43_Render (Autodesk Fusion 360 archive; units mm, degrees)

design "43 Render"
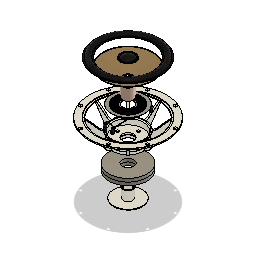
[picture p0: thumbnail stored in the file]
part number: 6 Inch Woofer
parameter "VoiceCoilDia" = 30
parameter "VoiceCoilThickness" = 2
parameter "PoleDia" = 22 (= "VoiceCoilDia + -4 * VoiceCoilThickness")
parameter "BasketThickness" = 3
parameter "SpiderMountingSurface" = 46 (= "SpacerDiameter / 2 + 2 * BasketThickness")
parameter "adsk_nomlen" = 10
parameter "adsk_headh" = 2.7
parameter "adsk_headdia" = 9.3
parameter "adsk_nomdia" = 5
parameter "adsk_headang" = 90
parameter "adsk_phildia" = 5.2
parameter "adsk_philwidth" = 0.66
parameter "adsk_phildepth" = 3.2
parameter "adsk_shnkdia" = 4.5092
parameter "adsk_thrlen" = 5.7
parameter "adsk_pitch1" = 0.8
parameter "adsk_startlen" = 0.4908
parameter "adsk_midfillet" = 0.5 (= "adsk_nomdia * 0.1")
parameter "adsk_endpointdia" = 4.0185
parameter "MountingHoleDia" = 86.2 (= "( ( SpeakerSize * 25.4 / 2 ) * 1 mm ) + ( FlangeSize / 2 )")
parameter "ConeAngle" = 70
parameter "CoverThickness" = 2.5
sketch "Sketch1" plane through (0, 0, 0) normal (0, 1, 0) x axis (1, 0, 0)
  circle C1 centre (0, 0) radius 50
  circle C2 centre (0, 0) radius 18
  point P1 (0, 0)
  point P2 (0, 0)
  point P3 (0, 0)
  coincident P1 P2
  coincident P1 P3
  dimension "MagnetDia" diameter C1 = 100
  dimension "MagnetThruHole" diameter C2 = 36 (= "VoiceCoilDia + 3 * VoiceCoilThickness")
extrude "Extrude1" new body sketch "Sketch1" along normal blind 10 named "MagnetThickness"
as_built_joint "As-built1"
chamfer "Chamfer2" distance 0.5
rectangular_pattern "R-Pattern1" uSpaceDistance 10 (= "MagnetThickness") vSpaceDistance 0
sketch "Sketch1" plane through (0, 0, 0) normal (0, -1, 0) x axis (1, 0, 0)
  circle C1 centre (0, 0) radius 18
  circle C2 centre (0, 0) radius 37.5
  circle C3 centre (0, 0) radius 18
  circle C4 centre (0, 0) radius 6
  circle C5 centre (0, 0) radius 49.5
  concentric C1 C2
  concentric C2 C3
  concentric C2 C4
  dimension "BottomPlateDiameter" diameter C2 = 75 (= "MagnetDia * 0.75")
  dimension "d12" diameter C3 = 36 (= "MagnetThruHole")
  dimension "VentHole" diameter C4 = 12 (= "VoiceCoilDia / 2.5")
extrude "Extrude1" new body sketch "Sketch1" profile of C1 C2 C3 C4 along normal blind 9 (= "VentHole * 0.75") named "BottomPlateThickness"
fillet "Fillet1" radius 37.5 (= "BottomPlateDiameter / 2")
extrude "Extrude2" add of existing geometry blind 2 named "BottomPlateOffset"
fillet "Fillet2" radius 3 (= "VentHole / 4")
sketch "Sketch4" plane through (0, 2, 0) normal (0, 1, 0) x axis (-1, 0, 0)
  circle C1 centre (0, 0) radius 37.5
  circle C2 centre (0, 0) radius 15
  circle C3 centre (0, 0) radius 11
  circle C4 centre (0, 0) radius 9
  point P1 (0, 0)
  point P3 (0, 0)
  point P4 (0, 0)
  coincident P1 P3
  coincident P1 P4
  dimension "d23" diameter C2 = 30 (= "VoiceCoilDia")
  dimension "d24" diameter C3 = 22 (= "PoleDia")
extrude "Extrude3" add sketch "Sketch4" profile of C2 C3 along normal blind 30 (= "( MagnetCount + 1 ) * MagnetThickness") named "PoleLength"
chamfer "Chamfer1" distance 1
joint "Assemble" alignAngle 0 alignOffsetX 0 alignOffsetY 0 alignOffsetZ 0
sketch "Sketch1" plane through (0, 0, 0) normal (0, 1, 0) x axis (1, 0, 0)
  line L1 (0, 18) -> (0, 0)
  line L2 (0, 40) -> (0, 18)
  circle C1 centre (0, 0) radius 18
  circle C2 centre (0, 0) radius 40
  circle C3 centre (0, 0) radius 29
  point P1 (0, 0)
  point P2 (0, 0)
  point P3 (0, 0)
  point P4 (0, 0)
  point P5 (0, 18)
  point P6 (0, 40)
  point P8 (0, 29)
  coincident P1 P2
  coincident P1 P3
  coincident P2 P4
  coincident C1 P5
  vertical L1
  coincident C2 P6
  parallel L1 L2
  concentric C2 C3
  midpoint L2 P8
  coincident C3 P8
  dimension "d32" diameter C1 = 36 (= "MagnetThruHole")
  dimension "SpacerDiameter" diameter C2 = 80 (= "MagnetDia * 0.8")
extrude "Extrude1" new body sketch "Sketch1" profile of C1 C2 along normal blind 10 (= "MagnetThickness")
hole "Hole1" HoleDepth 10 (= "MagnetThickness") HoleDiameter 4.234 TipAngle 118
circular_pattern "C-Pattern1" countU 3 (= "SpeakerSize / 2") TotalAngle 360
chamfer "Chamfer1" distance 1
joint "Assemble" alignAngle 0 alignOffsetX 0 alignOffsetY 0 alignOffsetZ 0
sketch "Sketch1" plane through (0, 0, 0) normal (0, 1, 0) x axis (1, 0, 0)
  circle C1 centre (0, 0) radius 43
  circle C2 centre (0, 0) radius 18
  circle C3 centre (0, 29) radius 2.117
  point P1 (0, 0)
  point P2 (0, 0)
  point P3 (0, 0)
  coincident P1 P2
  coincident P1 P3
  dimension "d47" diameter C1 = 86 (= "SpacerDiameter + 2 * BasketThickness")
  dimension "d48" diameter C2 = 36 (= "MagnetThruHole")
extrude "Extrude1" new body sketch "Sketch1" against normal blind 5 (magnitude of "MagnetThickness / -2")
hole "Hole1" HoleDepth 10 HoleDiameter 5.5 TipAngle 118 CSDiameter 10.4 CSAngle 90
circular_pattern "C-Pattern1" countU 3 (= "SpeakerSize / 2") TotalAngle 360
joint "Assemble" alignAngle 0 alignOffsetX 0 alignOffsetY 0 alignOffsetZ 0
work_plane "WorkPlane1" RotateAngle 30 (= "90.0 deg - ( ( 360 / SpeakerSize ) * 1 deg )")
sketch "Sketch3" plane through (0, -22.875, 0) normal (0.5, 0, 0.866) x axis (0, 1, 0)
  line L1 (17.875, -43) -> (17.875, 43)
  line L2 (22.875, 43) -> (22.875, -43)
  line L3 (17.875, 18) -> (17.875, -18)
  line L4 (22.875, -18) -> (22.875, 18)
  line L5 (22.875, 18) -> (22.875, -18)
  line L6 (100, 0) -> (22.875, 0)
  line L7 (42.875, -46) -> (42.875, -43)
  line L8 (22.875, -46) -> (42.875, -46)
  line L9 (22.875, -43) -> (22.875, -46)
  line L10 (42.875, -43) -> (42.875, -46)
  line L11 (39.875, -46) -> (42.875, -46)
  line L12 (39.875, -43) -> (39.875, -46)
  line L13 (22.875, -43) -> (39.875, -43)
  line L14 (22.875, -40) -> (22.875, -43)
  line L15 (39.875, -40) -> (22.875, -40)
  line L16 (17.875, -53.0255) -> (17.875, -43)
  line L17 (60.975, -77.8667) -> (17.875, -53.0255)
  line L18 (60.975, -71.2) -> (46.9451, -56.2731)
  line L19 (60.975, -93.7) -> (60.975, -78.7)
  line L20 (65.475, -96.2) -> (60.975, -96.2)
  line L21 (65.475, -76.2) -> (65.475, -96.2)
  line L22 (60.975, -76.2) -> (65.475, -76.2)
  line L23 (60.975, -96.2) -> (60.975, -76.2)
  line L24 (22.875, -43) -> (17.875, -43)
  line L25 (17.875, -40) -> (17.875, -43)
  line L26 (22.875, -40) -> (17.875, -40)
  line L27 (63.225, -76.2) -> (60.975, -76.2)
  line L28 (63.225, -71.2) -> (63.225, -76.2)
  line L29 (60.975, -71.2) -> (63.225, -71.2)
  line L30 (60.975, -76.2) -> (60.975, -71.2)
  arc A1 centre (39.875, -43) radius 3 clockwise from (39.875, -40) to (42.875, -43)
  arc A2 centre (57.875, -46) radius 15 clockwise from (46.9451, -56.2731) to (42.875, -46)
  point P9 (22.875, -18)
  point P10 (22.875, -18)
  point P8 (22.875, 18)
  point P11 (22.875, 18)
  point P12 (22.875, 0)
  point P14 (42.875, 0)
  point P4 (22.875, -43)
  point P17 (22.875, -43)
  point P19 (22.875, -43)
  point P20 (22.875, -43)
  point P3 (17.875, -43)
  point P27 (17.875, -43)
  point P28 (60.975, -93.7)
  point P34 (60.975, -93.7)
  point P29 (60.975, -78.7)
  point P35 (60.975, -78.7)
  point P36 (60.975, -86.2)
  point P42 (17.875, -43)
  point P43 (17.875, -40)
  point P47 (60.975, -77.8667)
  point P15 (42.875, -46)
  point P39 (42.875, -46)
  point P22 (39.875, -43)
  point P26 (39.875, -43)
  point P23 (39.875, -43)
  point P37 (17.875, -53.0255)
  point P38 (17.875, -53.0255)
  point P16 (22.875, -46)
  point P18 (39.875, -46)
  point P30 (60.975, -96.2)
  point P31 (65.475, -96.2)
  point P32 (65.475, -76.2)
  point P33 (60.975, -76.2)
  point P44 (63.225, -76.2)
  point P45 (63.225, -71.2)
  point P46 (60.975, -71.2)
  coincident P9 P10
  coincident P8 P11
  midpoint L2 P12
  perpendicular L5 L6
  coincident L6 P14
  perpendicular L6 L7
  perpendicular L2 L8
  coincident P4 P17
  perpendicular L8 L9
  perpendicular L8 L10
  perpendicular L7 L11
  coincident P4 P19
  perpendicular L9 L13
  vertical L12
  coincident P4 P20
  perpendicular L13 L14
  horizontal L15
  coincident P14 L7
  tangent L7 A1
  tangent L15 A1
  coincident P3 P27
  parallel L1 L16
  vertical L19
  perpendicular L20 L21
  perpendicular L21 L22
  coincident P28 P34
  coincident P29 P35
  midpoint L19 P36
  perpendicular L20 L23
  midpoint P36 L23
  tangent L18 A2
  coincident P3 P42
  coincident L1 P43
  parallel L1 L25
  horizontal L26
  horizontal L27
  vertical L28
  horizontal L29
  vertical L30
  coincident L23 P47
  coincident P15 P39
  tangent L7 A2
  coincident P22 P26
  coincident P23 P26
  coincident P37 P38
  dimension "SpiderDepth" distance P15 P16 = 20
  dimension "d70" distance P15 P18 = 3 (= "BasketThickness")
  dimension "d73" radius A1 = 3 (= "BasketThickness")
  dimension "d75" distance P30 P31 = 4.5 (= "BasketThickness * 1.5")
  dimension "d77" distance L6 L22 = 76.2 (= "( SpeakerSize * 25.4 / 2 ) * 1 mm")
  dimension "FlangeSize" distance P31 P32 = 20
  dimension "d79" distance P34 P35 = 15 (= "FlangeSize * 0.75")
  dimension "d80" distance L2 L23 = 38.1 (= "( SpeakerSize * 25.4 / 4 ) * 1 mm")
  dimension "d84" radius A2 = 15
  dimension "d95" distance P33 P44 = 2.25 (= "BasketThickness * 0.75")
  dimension "d96" distance P44 P45 = 5 (= "FlangeSize / 4")
  dimension "d178" distance P46 P47 = 6.6667 (= "FlangeSize / 3")
  dimension "d252" distance L15 L24 = 3 (= "BasketThickness")
  dimension "d254" angle L17 L18 = 16.817
  dimension "d259" distance L6 L11 = 46 (= "SpiderMountingSurface")
revolve "Revolve1" sketch "Sketch3" AlongAngle 360
fillet "Fillet2" radius 3 (= "BasketThickness")
chamfer "Chamfer1" distance 1 distance 0.5
extrude "Extrude2" add sketch "Sketch3" profile of L1 L2 L10 L11 L12 L13 L14 L15 A1 L16 L17 L18 L19 L23 A2 L24 L25 L26 along a picked direction distance 3 (= "BasketThickness")
fillet "Fillet3" radius 12 (= "BasketThickness * 4")
chamfer "Chamfer2" distance 0.5
circular_pattern "C-Pattern2" TotalAngle 360
sketch "Sketch4" plane through (0, 42.6, 0) normal (0, 1, 0) x axis (-1, 0, 0)
  line L1 (0, -125) -> (0, 0)
  line L2 (-44.35, -76.8165) -> (0, 0)
  line L3 (-48.1, -83.3116) -> (-44.35, -76.8165)
  circle C1 centre (0, 0) radius 76.7
  circle C2 centre (0, 0) radius 95.7
  circle C3 centre (0, 0) radius 96.2
  point P1 (0, 0)
  point P3 (0, 0)
  point P5 (0, 0)
  point P8 (-48.1, -83.3116)
  point P6 (-44.35, -76.8165)
  coincident P1 P3
  vertical L1
  coincident P1 P5
  coincident C3 P8
  parallel L2 L3
  dimension "d97" angle L1 L2 = 30 (= "( 180 / SpeakerSize ) * 1 deg")
  dimension "d181" distance P6 P8 = 7.5
hole "Hole2" HoleDepth 20 HoleDiameter 5.5 TipAngle 118 CSDiameter 10.4 CSAngle 90
circular_pattern "C-Pattern3" countU 12 TotalAngle 360
sketch "Sketch1" plane through (0, 0, 0) normal (0, 0, 1) x axis (1, 0, 0)
  line L1 (0, 140.5455) -> (0, 0)
  line L2 (71.2, 76.35) -> (75.95, 76.35)
  line L3 (71.2, 75.35) -> (71.2, 76.35)
  line L4 (76.2, 75.35) -> (71.2, 75.35)
  line L5 (76.2, 76.1) -> (76.2, 75.35)
  line L6 (56.2, 76.35) -> (51.45, 76.35)
  line L7 (56.2, 75.35) -> (56.2, 76.35)
  line L8 (51.2, 75.35) -> (56.2, 75.35)
  line L9 (51.2, 76.1) -> (51.2, 75.35)
  line L10 (71.2, 75.35) -> (56.2, 75.35)
  line L11 (0, 50.963) -> (51.2, 75.35)
  line L12 (15, 58.1076) -> (51.2, 75.35)
  line L13 (15.285, 57.1357) -> (53.5255, 75.35)
  line L14 (15, 55.25) -> (15, 56.6843)
  line L15 (14.57, 57.9028) -> (15, 58.1076)
  line L16 (14, 55.25) -> (14, 57)
  line L17 (14.75, 55) -> (14.25, 55)
  line L18 (30.3147, 35) -> (19.9147, 35)
  line L19 (-19.9147, 35) -> (-30.3147, 35)
  line L20 (5.2, 35) -> (-5.2, 35)
  line L21 (-39, 20) -> (39, 20)
  line L22 (-40, 35) -> (40, 35)
  line L23 (18, 35) -> (-18, 35)
  circle C1 centre (63.7, 75.35) radius 7.5664
  circle C2 centre (63.7, 75.35) radius 8.5664
  arc A1 centre (75.95, 76.1) radius 0.25 clockwise from (75.95, 76.35) to (76.2, 76.1)
  arc A2 centre (51.45, 76.1) radius 0.25 clockwise from (51.2, 76.1) to (51.45, 76.35)
  arc A3 centre (15.5, 56.6843) radius 0.5 clockwise from (15, 56.6843) to (15.285, 57.1357)
  arc A4 centre (15, 57) radius 1 clockwise from (14, 57) to (14.57, 57.9028)
  arc A5 centre (14.75, 55.25) radius 0.25 clockwise from (15, 55.25) to (14.75, 55)
  arc A6 centre (14.25, 55.25) radius 0.25 clockwise from (14.25, 55) to (14, 55.25)
  point P1 (0, 0)
  point P2 (0, 0)
  point P6 (71.2, 75.35)
  point P10 (56.2, 75.35)
  point P12 (63.7, 75.35)
  point P9 (56.2, 76.35)
  point P14 (56.1336, 75.35)
  point P15 (55.1336, 75.35)
  point P16 (0, 50.963)
  point P17 (15, 58.1076)
  point P4 (76.2, 76.35)
  point P8 (51.2, 76.35)
  point P24 (53.5255, 75.35)
  point P25 (15, 57)
  point P26 (15, 55)
  point P7 (76.2, 75.35)
  point P11 (51.2, 75.35)
  coincident P1 P2
  vertical L1
  horizontal L2
  vertical L3
  horizontal L4
  vertical L5
  horizontal L6
  vertical L7
  horizontal L8
  vertical L9
  horizontal P6 P10
  midpoint L10 P12
  coincident P9 C1
  concentric C1 C2
  coincident C1 P14
  coincident L8 P14
  coincident L8 P15
  coincident C2 P15
  coincident L1 P16
  coincident L11 P17
  coincident P4 L2
  coincident P4 L5
  tangent L2 A1
  tangent L5 A1
  coincident P8 L6
  coincident P8 L9
  tangent L6 A2
  tangent L9 A2
  coincident L8 P24
  parallel L12 L13
  vertical P17 P25
  vertical L14
  parallel L14 L16
  horizontal L17
  coincident P25 L13
  coincident P25 L14
  tangent L13 A3
  tangent L14 A3
  tangent L15 A4
  tangent L16 A4
  parallel L12 L15
  coincident P26 L14
  coincident P26 L17
  tangent L14 A5
  tangent L17 A5
  tangent L16 A6
  tangent L17 A6
  equal A5 A6
  dimension "SurroundThickness" distance P4 P7 = 1
  dimension "d107" distance P8 P11 = 1 (= "SurroundThickness")
  dimension "d108" distance P6 P7 = 5 (= "FlangeSize / 4")
  dimension "d109" distance P10 P11 = 5 (= "FlangeSize / 4")
  dimension "SurroundSize" distance L3 L7 = 15 (= "FlangeSize * 0.75")
  dimension "d111" distance P14 P15 = 1 (= "SurroundThickness")
  dimension "d112" distance L1 L5 = 76.2 (= "( SpeakerSize * 25.4 / 2 ) * 1 mm")
  dimension "d117" radius A1 = 0.25
  dimension "d118" radius A2 = 0.25
  dimension "d119" distance L12 L13 = 1 (= "SurroundThickness")
  dimension "d120" distance P25 P26 = 2 (= "SurroundThickness * 2")
  dimension "d121" distance L14 L16 = 1 (= "SurroundThickness")
  dimension "d122" radius A3 = 0.5 (= "SurroundThickness / 2")
  dimension "d123" radius A4 = 1 (= "SurroundThickness")
  dimension "d124" radius A5 = 0.25 (= "SurroundThickness / 4")
  dimension "d141" distance L1 L14 = 15 (= "VoiceCoilDia / 2")
  dimension "d144" distance L17 L21 = 35 (= "VoiceCoilLength")
  dimension "d282" distance P1 L4 = 75.35 (= "Linear Dimension-14")
revolve "Revolve1" sketch "Sketch1" AlongAngle 360
sketch "Sketch1" plane through (0, 0, 0) normal (0, 0, 1) x axis (1, 0, 0)
  line L1 (0, 104.734) -> (0, 0)
  line L2 (36.8, 55) -> (44.5, 55)
  line L3 (36.8, 56) -> (36.8, 55)
  line L4 (44.5, 56) -> (36.8, 56)
  line L5 (44.5, 55) -> (44.5, 56)
  line L6 (15, 55) -> (17, 55)
  line L7 (15, 20) -> (15, 55)
  line L8 (17, 20) -> (15, 20)
  line L9 (17, 55) -> (17, 20)
  line L10 (-39, 20) -> (39, 20)
  line L11 (17, 55) -> (15, 55)
  line L12 (17, 56.5) -> (17, 55)
  line L13 (15, 56.5) -> (17, 56.5)
  line L14 (15, 55) -> (15, 56.5)
  line L15 (17, 55.5) -> (36.8, 55.5)
  line L16 (17, 56) -> (36.8, 56)
  line L17 (17, 55) -> (17, 56)
  line L18 (36.8, 55) -> (17, 55)
  line L19 (36.8, 56) -> (36.8, 55)
  line L20 (17, 55) -> (36.8, 56)
  line L21 (36.8, 55) -> (17, 56)
  line L22 (43, 55) -> (-43, 55)
  circle C1 centre (26.9, 55.5) radius 1
  circle C2 centre (24.6, 55.5) radius 1
  circle C3 centre (22.3, 55.5) radius 1
  circle C4 centre (20, 55.5) radius 1
  circle C5 centre (29.2, 55.5) radius 1
  circle C6 centre (31.5, 55.5) radius 1
  circle C7 centre (33.8, 55.5) radius 1
  circle C8 centre (36.1, 55.5) radius 1
  point P1 (0, 0)
  point P2 (0, 0)
  point P11 (17, 20)
  point P16 (36.8, 55.5)
  point P17 (17, 55.5)
  point P21 (26.9, 55.5)
  point P22 (26.9, 55.5)
  point P4 (44.5, 55)
  point P7 (44.5, 56)
  point P8 (17, 55)
  point P9 (15, 55)
  point P14 (17, 56.5)
  coincident P1 P2
  vertical L1
  horizontal L2
  vertical L3
  horizontal L4
  vertical L5
  horizontal L6
  vertical L7
  horizontal L8
  vertical L9
  coincident P11 L10
  horizontal L11
  vertical L12
  horizontal L13
  vertical L14
  midpoint L3 P16
  coincident L12 P17
  perpendicular L12 L15
  horizontal L16
  perpendicular L16 L17
  parallel L16 L18
  parallel L17 L19
  coincident L20 P21
  coincident L21 P21
  midpoint L15 P21
  coincident P21 P22
  dimension "SpiderThickness" distance P4 P7 = 1
  dimension "d134" distance P1 L2 = 55
  dimension "d135" distance L1 L3 = 36.8 (= "SpiderMountingSurface * 0.8")
  dimension "d137" distance L1 L7 = 15 (= "VoiceCoilDia / 2")
  dimension "d138" distance P8 P9 = 2 (= "VoiceCoilThickness")
  dimension "VoiceCoilLength" distance P8 P11 = 35 (= "SpiderDepth + MagnetThickness * 1.5")
  dimension "d145" distance P8 P14 = 1.5 (= "SurroundThickness * 1.5")
  dimension "d146" diameter C1 = 2 (= "SpiderThickness * 2")
  dimension "SpiderRad" distance L1 L5 = 44.5 (= "SpiderMountingSurface - BasketThickness / 2")
  dimension "d149" R-Pattern1-uDistance = 2.3 (= "( SpiderMountingSurface / 20 )")
  dimension "d150" R-Pattern1-vDistance = 0
  dimension "d154" R-Pattern2-uDistance = -2.3 (= "-( SpiderMountingSurface / 20 )")
  dimension "d155" R-Pattern2-vDistance = 0
revolve "Revolve1" sketch "Sketch1" AlongAngle 360
revolve "Revolve2" sketch "Sketch1" AlongAngle 360 bodies "Voice Coil"
fillet "Fillet1" radius 0.25 (= "SpiderThickness / 4")
work_plane "WorkPlane3" AlongDistance -52 (= "-( ( SpiderMountingSurface - BasketThickness / 2 ) + ( 7.5 mm ) )")
sketch "Sketch3" plane through (0, 56, 0) normal (0, 1, 0) x axis (-1, 0, 0)
  line L1 (12, -52) -> (12, -10.9545)
  line L2 (11, -10.9545) -> (13, -10.9545)
  line L3 (11, -48.127) -> (11, -10.9545)
  line L4 (13, -10.9545) -> (13, -48.127)
  line L5 (10.9766, -94.0045) -> (13, -10.9545)
  line L6 (12.997, -92.9231) -> (11, -10.9545)
  line L7 (-13, -10.9545) -> (-13, -48.127)
  line L8 (-11, -10.9545) -> (-13, -10.9545)
  line L9 (-11, -48.127) -> (-11, -10.9545)
  line L10 (19, 0) -> (0, 0)
  line L11 (-19, 0) -> (0, 0)
  line L12 (0, -12) -> (0, 0)
  line L13 (-21.75, -52) -> (-0.75, -52)
  circle C1 centre (0, 0) radius 19.134
  circle C2 centre (12, -52) radius 4
  circle C3 centre (-12, -52) radius 4
  circle C4 centre (0, 0) radius 17
  circle C5 centre (0, 0) radius 19
  point P4 (12, -52)
  point P5 (12, -52)
  point P10 (12, -52)
  point P11 (13, -48.127)
  point P12 (11, -48.127)
  point P14 (-13, -10.9545)
  point P18 (0, 0)
  point P20 (0, 0)
  point P21 (19, 0)
  point P22 (0, 0)
  point P23 (-19, 0)
  point P19 (0, 0)
  point P24 (0, 0)
  point P6 (13, -10.9545)
  point P3 (12, -10.9545)
  point P7 (11, -10.9545)
  point P15 (-11, -10.9545)
  point P13 (-13, -48.127)
  point P16 (-11, -48.127)
  point P26 (-0.75, -52)
  vertical L1
  coincident P4 P5
  horizontal L2
  perpendicular L2 L3
  parallel L3 L4
  coincident L5 P10
  coincident L6 P10
  coincident P5 P10
  coincident C2 P11
  coincident C2 P12
  coincident P14 C4
  coincident P18 P20
  coincident C5 P21
  coincident P18 P22
  coincident C5 P23
  coincident P19 P24
  perpendicular L10 L12
  coincident P6 C4
  midpoint P3 L2
  symmetric C2 C3 L12
  symmetric L4 L7 L12
  symmetric L3 L9 L12
  symmetric P7 P15 L12
  coincident P13 C3
  coincident P16 C3
  horizontal P5 P26
  dimension "d159" diameter C2 = 8
  dimension "TinselLeadWidth" distance P6 P7 = 2
  dimension "d232" distance C4 C5 = 2 (= "TinselLeadWidth")
  dimension "d263" distance L1 L12 = 12
component_from_bodies "Body->Comp2"
extrude "Extrude1" sketch "Sketch3" profile of C1 C2 L3 L4 L7 L9 C3 C4 C5 L10 L11 blind 0.5 named "TinselLeadThickness" from offset -0.5 bodies "TinselLeads"
extrude "Extrude2" sketch "Sketch3" profile of C2 C3 L13 blind 1.5 (= "TinselLeadThickness * 3") second side blind 15 (= "TinselLeadThickness * 30") from offset -0.5 bodies "Terminals"
work_plane "WorkPlane1" RotateAngle 270
sketch "Sketch4" plane through (-12, 53.5787, -56) normal (0, 0, -1) x axis (-1, 0, 0)
  line L1 (-24, -12.5787) -> (-24, -7.5787)
  line L2 (0, -12.5787) -> (0, -7.5787)
  line L3 (4, -12.5787) -> (-4, -12.5787)
  line L4 (-20, -12.5787) -> (-28, -12.5787)
  circle C1 centre (-24, -7.5787) radius 2.5
  circle C2 centre (0, -7.5787) radius 2.5
  point P2 (-24, -7.5787)
  point P4 (-24, -7.5787)
  point P3 (0, -7.5787)
  point P6 (0, -7.5787)
  point P5 (-24, -12.5787)
  point P7 (0, -12.5787)
  coincident P2 P4
  coincident P3 P6
  vertical L2
  midpoint P5 L4
  perpendicular L1 L4
  midpoint P7 L3
  dimension "WireGauge" diameter C1 = 5
  dimension "d182" diameter C2 = 5
  dimension "d183" distance P4 P5 = 5 (= "WireGauge")
  dimension "d184" distance P6 P7 = 5 (= "WireGauge")
extrude "Extrude3" cut sketch "Sketch4" profile of C1 C2 against normal blind 8
sketch "Sketch1" plane through (0, 0, 0) normal (0, 0, 1) x axis (1, 0, 0)
  line L1 (0, 50.963) -> (51.2, 75.35)
  line L2 (0, 55.963) -> (0, 50.963)
  line L3 (22.3021, 61.5857) -> (27.7191, 64.1658)
  line L4 (26.859, 65.9715) -> (27.7191, 64.1658)
  line L5 (23.5372, 64.3893) -> (26.859, 65.9715)
  line L6 (0, 80.963) -> (0, 50.963)
  line L7 (14.57, 57.9028) -> (22.3021, 61.5857)
  circle C1 centre (0, 55.963) radius 23
  circle C2 centre (0, 55.963) radius 25
  point P3 (0, 50.963)
  point P4 (0, 50.963)
  point P6 (27.7191, 64.1658)
  point P7 (22.3021, 61.5857)
  point P5 (0, 55.963)
  point P9 (0, 55.963)
  point P11 (23.5372, 64.3893)
  point P12 (0, 50.963)
  point P13 (0, 80.963)
  point P14 (14.57, 57.9028)
  point P15 (14.57, 57.9028)
  point P8 (26.859, 65.9715)
  point P10 (0, 55.963)
  coincident P3 P4
  vertical L2
  coincident L1 P6
  coincident L1 P7
  parallel L1 L3
  perpendicular L1 L4
  coincident P5 P9
  coincident P7 C1
  concentric C1 C2
  coincident C2 P11
  perpendicular L4 L5
  coincident P3 P12
  coincident C2 P13
  vertical L6
  coincident P14 P15
  dimension "DustCapThickness" distance C1 C2 = 2
  dimension "d193" distance P6 P8 = 2 (= "DustCapThickness")
  dimension "d194" distance P6 P7 = 6 (= "DustCapThickness * 3")
  dimension "DustCapCurve" diameter C2 = 50
  dimension "DustCapOffset" distance P10 P12 = 5
sketch "Sketch5" plane through (0, 56, 0) normal (0, 1, 0) x axis (-1, 0, 0)
  line L1 (-12, -229.6377) -> (-12, -54.8723)
  line L2 (12, -611.627) -> (12, -54.8723)
  line L3 (-10, -54.8723) -> (-10, -44.8999)
  line L4 (-14, -54.8723) -> (-10, -54.8723)
  line L5 (-14, -43.8178) -> (-14, -54.8723)
  line L6 (-10, -54.8723) -> (-8311.3248, -725447.2893)
  line L7 (-14, -54.8723) -> (3910.1152, -342954.7674)
  line L8 (10, -54.8723) -> (10, -44.8999)
  line L9 (14, -54.8723) -> (10, -54.8723)
  line L10 (14, -43.8178) -> (14, -54.8723)
  line L11 (10, -54.8723) -> (9.739, 17.7761)
  line L12 (14, -54.8723) -> (-1217.7809, -342954.7674)
  line L13 (15.5, -52) -> (12, -52)
  line L14 (8.5, -52) -> (12, -52)
  line L15 (-8.5, -52) -> (-12, -52)
  line L16 (-15.5, -52) -> (-12, -52)
  circle C1 centre (12, -52) radius 4
  circle C2 centre (-12, -52) radius 4
  circle C3 centre (0, 0) radius 34.666
  arc A1 centre (-12, -52) radius 3.5 clockwise from (-15.5, -52) to (-8.5, -52)
  arc A2 centre (12, -52) radius 3.5 clockwise from (8.5, -52) to (15.5, -52)
  circle C4 centre (0, 0) radius 46
  circle C5 centre (0, 0) radius 44.25
  arc A3 centre (0, 0) radius 46 clockwise from (38.2524, -25.5491) to (3, -45.9021)
  circle C6 centre (0, 0) radius 35.234
  circle C7 centre (0, 0) radius 36.966
  arc A4 centre (0, 0) radius 46 clockwise from (-41.2524, -20.353) to (-41.2524, 20.353)
  arc A5 centre (0, 0) radius 46 clockwise from (-41.2524, -20.353) to (-41.2524, 20.353)
  arc A6 centre (0, 0) radius 46 clockwise from (3, 45.9021) to (38.2524, 25.5491)
  arc A7 centre (0, 0) radius 46 clockwise from (3, 45.9021) to (38.2524, 25.5491)
  point P10 (-12, -229.6377)
  point P3 (-12, -229.6377)
  point P15 (12, -611.627)
  point P5 (12, -611.627)
  point P17 (12, -52)
  point P18 (-12, -52)
  point P7 (3910.1152, -342954.7674)
  point P12 (-1217.7809, -342954.7674)
  point P2 (-12, -54.8723)
  point P4 (12, -54.8723)
  point P26 (12, -52)
  point P28 (12, -52)
  point P30 (-12, -52)
  point P32 (-12, -52)
  point P8 (-10, -54.8723)
  point P14 (14, -54.8723)
  point P22 (14, -43.8178)
  point P23 (10, -44.8999)
  point P21 (-10, -44.8999)
  point P20 (-14, -43.8178)
  point P9 (-14, -54.8723)
  point P13 (10, -54.8723)
  point P31 (-8.5, -52)
  point P29 (8.5, -52)
  vertical L1
  parallel L1 L2
  parallel L3 L5
  coincident L6 P10
  coincident L7 P10
  coincident P3 P10
  parallel L8 L10
  coincident L11 P15
  coincident L12 P15
  coincident P5 P15
  coincident L2 P17
  coincident L1 P18
  horizontal P7 P12
  vertical L8
  vertical L3
  horizontal L9
  horizontal L4
  midpoint P2 L4
  midpoint P4 L9
  coincident P17 P26
  horizontal L13
  coincident P17 P28
  parallel L13 L14
  coincident P18 P30
  parallel L13 L15
  coincident P18 P32
  parallel L15 L16
  concentric C2 A1
  concentric C1 A2
  coincident P8 A1
  coincident P14 A2
  concentric C3 C4
  coincident P22 C4
  coincident P23 C4
  coincident P21 C4
  coincident P20 C4
  dimension "d185" distance P8 P9 = 4 (= "TinselLeadWidth * 2")
  dimension "d186" distance P13 P14 = 4 (= "TinselLeadWidth * 2")
  dimension "d291" distance P18 P31 = 3.5
  dimension "d292" distance P28 P29 = 3.5
  dimension "d293" diameter C4 = 92 (= "2 * ( SpiderMountingSurface - BasketThickness / 2 ) + BasketThickness")
extrude "Extrude4" sketch "Sketch5" profile of L3 L5 L8 L10 C1 C2 C4 blind 1 from offset -3 (= "-SpiderThickness - ( BasketThickness / 2 ) - 0.5 mm")
component_from_bodies "Body->Comp1"
joint "Assemble10" alignAngle 0 alignOffsetX 0 alignOffsetY 0 alignOffsetZ 0
joint "Assemble5" alignAngle 0 alignOffsetX 0 alignOffsetY 0 alignOffsetZ 0
revolve "Revolve1" sketch "Sketch1" AlongAngle 360
fillet "Fillet1" radius 1 (= "DustCapThickness / 2")
revolve "Revolve1" sketch "Sketch1" AlongAngle 360
component_from_bodies "Body->Comp1"
joint "Assemble" alignAngle 0 alignOffsetX 0 alignOffsetY 0 alignOffsetZ 0
joint "Assemble" alignAngle 0 alignOffsetX 0 alignOffsetY 0 alignOffsetZ 0
joint "Assemble" alignAngle 0 alignOffsetX 0 alignOffsetY 0 alignOffsetZ 0
as_built_joint "As-built2"
chamfer "Chamfer2" distance 0.5
work_plane "WorkPlane2" AlongDistance -4
sketch "Sketch7" plane through (-12, 53.5787, -52) normal (0, 0, -1) x axis (-1, 0, 0)
  line L1 (-20.5, 3.9213) -> (-27.5, 3.9213)
  line L2 (3.5, 3.9213) -> (-3.5, 3.9213)
  line L3 (-24, 5.4213) -> (-24, 3.9213)
  line L4 (-3.5, 8.9213) -> (-20.5, 8.9213)
  line L5 (0, 3.9213) -> (0, 5.4213)
  arc A1 centre (-20.5, 5.4213) radius 3.5 clockwise from (-24, 5.4213) to (-20.5, 8.9213)
  arc A2 centre (-3.5, 5.4213) radius 3.5 clockwise from (-3.5, 8.9213) to (0, 5.4213)
  point P6 (-24, 3.9213)
  point P8 (0, 3.9213)
  point P7 (-24, 8.9213)
  midpoint L1 P6
  perpendicular L1 L3
  perpendicular L3 L4
  midpoint L2 P8
  vertical L5
  coincident P7 L3
  coincident P7 L4
  tangent L3 A1
  tangent L4 A1
  tangent L4 A2
  tangent L5 A2
  equal A1 A2
  dimension "d297" distance P6 P7 = 5
  dimension "d298" radius A1 = 3.5
pipe "Pipe2" SectionSize 2 SectionThickness 0.5
mirror "Mirror1" mirrorStitchTolerance 0.1 bodies "TinselLeads (1)", "Terminals (1)"
as_built_joint "As-built7"
canvas "Canvas4"
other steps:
base_feature "Base Feature1" bodies "Voice Coil"
base_feature "Base Feature1"
base_feature "Base Feature1"
thread "Thread1" ThreadOffset 0 ThreadDepth 10
create_component "CreateComponent1" alignAngle 0 alignOffsetX 0 alignOffsetY 0 alignOffsetZ 3.975 alignAngle 0 alignOffsetX 0 alignOffsetY 0 alignOffsetZ 3.975 alignAngle 0 alignOffsetX 0 alignOffsetY 0 alignOffsetZ 3.975 alignAngle 0 alignOffsetX 0 alignOffsetY 0 alignOffsetZ 3.975 alignAngle 0 alignOffsetX 0 alignOffsetY 0 alignOffsetZ 3.975 alignAngle 0 alignOffsetX 0 alignOffsetY 0 alignOffsetZ 3.975 alignAngle 0 alignOffsetX 0 alignOffsetY 0 alignOffsetZ 3.975 alignAngle 0 alignOffsetX 0 alignOffsetY 0 alignOffsetZ 3.975 alignAngle 0 alignOffsetX 0 alignOffsetY 0 alignOffsetZ 3.975
create_component "CreateComponent2"
joint_origin "JointOrigin1"
joint_origin "JointOrigin1"
create_component "CreateComponent3"
joint_origin "JointOrigin1"
joint_origin "JointOrigin2"
create_component "CreateComponent4"
joint_origin "JointOrigin1"
joint_origin "JointOrigin2"
create_component "CreateComponent5"
create_component "CreateComponent6"
create_component "CreateComponent7"
create_component "CreateComponent1"
create_component "CreateComponent2"
remove_body "RemoveBody1"
joint_origin "JointOrigin1"
joint_origin "JointOrigin1"
create_component "CreateComponent1"
remove_body "RemoveBody1"
create_component "CreateComponent2"
remove_body "RemoveBody2"
joint_origin "JointOrigin2"
joint_origin "JointOrigin4"
joint_origin "JointOrigin1"
joint_origin "JointOrigin2"
joint_origin "JointOrigin2"
joint_origin "JointOrigin5"
joint_origin "JointOrigin3"
joint_origin "JointOrigin6"
named bodies: "TinselLeads", "Body4 (1)", "Voice Coil", "Terminals", "TinselLeads (1)", "Terminals (1)"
